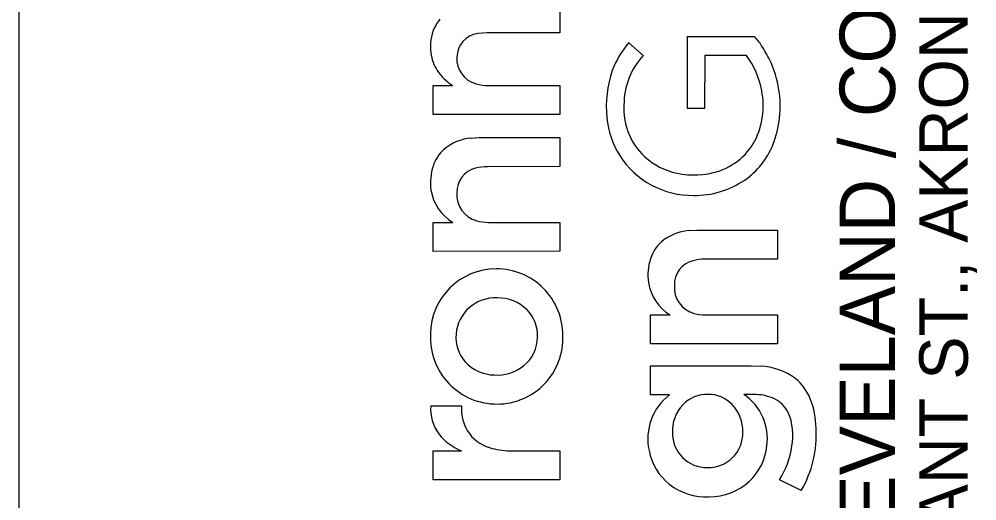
# Model space of a CAD drawing. Extents: x -0.4 to 34, y 0 to 22.
# Drawn here: x 32 to 32.984, y 3.094 to 3.59 of the extents above; entities that cross this region are included whole.
import ezdxf

# ---------------------------------------------------------------- set-up
doc = ezdxf.new("R2010")
doc.units = 0
doc.layers.add('SC_Scratch1', color=7, linetype='Continuous')
doc.layers.add('SH_Named_Boundary', color=7, linetype='Continuous')

msp = doc.modelspace()

# ---------------------------------------------------------------- linework, layer by layer
at = {"layer": 'SC_Scratch1'}
msp.add_line((32, 0.5), (32, 21.5), dxfattribs=at)
at = {"layer": 'SH_Named_Boundary'}
for p, q in [((32.55571, 3.60548), (32.55571, 3.57568)), ((32.4809, 3.57567), (32.47143, 3.57474)), ((32.55571, 3.57568), (32.4809, 3.57567)), ((32.62636, 3.56548), (32.64114, 3.55241)), ((32.6868, 3.57185), (32.75516, 3.57192)), ((32.6868, 3.49778), (32.6868, 3.57185)), ((32.70448, 3.55241), (32.70432, 3.49775)), ((32.74737, 3.55227), (32.70448, 3.55241)), ((32.42542, 3.49152), (32.42545, 3.52138)), ((32.42545, 3.52138), (32.44515, 3.52138)), ((32.48206, 3.52138), (32.55571, 3.52136)), ((32.55571, 3.52136), (32.55571, 3.49156)), ((32.70432, 3.49775), (32.6868, 3.49778)), ((32.75, 3.5), (32.75, 3.5)), ((32.55571, 3.49156), (32.42542, 3.49152)), ((32.46439, 3.46736), (32.47289, 3.46783)), ((32.47289, 3.46783), (32.55571, 3.46783)), ((32.55571, 3.46783), (32.55571, 3.43804)), ((32.55571, 3.43804), (32.4814, 3.43796)), ((32.42542, 3.38066), (32.44552, 3.38071)), ((32.42542, 3.35086), (32.42542, 3.38066)), ((32.48222, 3.38071), (32.55569, 3.38071)), ((32.55569, 3.38071), (32.55571, 3.35096)), ((32.68784, 3.3722), (32.69634, 3.37266)), ((32.69634, 3.37266), (32.77916, 3.37266)), ((32.77916, 3.37266), (32.77917, 3.34287)), ((32.55571, 3.35096), (32.42542, 3.35086)), ((32.77917, 3.34287), (32.70485, 3.3428)), ((32.64888, 3.2855), (32.66897, 3.28555)), ((32.64888, 3.25569), (32.64888, 3.2855)), ((32.70568, 3.28555), (32.77915, 3.28555)), ((32.77915, 3.28555), (32.77917, 3.25579)), ((32.77917, 3.25579), (32.64888, 3.25569)), ((32.6489, 3.20336), (32.64889, 3.23322)), ((32.64889, 3.23322), (32.75236, 3.23322)), ((32.75236, 3.23322), (32.76191, 3.23285)), ((32.66836, 3.20336), (32.6489, 3.20336)), ((32.75763, 3.20356), (32.74487, 3.20361)), ((32.42299, 3.19193), (32.45454, 3.19193)), ((32.42542, 3.14577), (32.45473, 3.14579)), ((32.42542, 3.11593), (32.42542, 3.14577)), ((32.50413, 3.14581), (32.55571, 3.14573)), ((32.55571, 3.14573), (32.55565, 3.11593)), ((32.55565, 3.11593), (32.42542, 3.11593)), ((32.8036, 3.10491), (32.7812, 3.11598))]:
    msp.add_line(p, q, dxfattribs=at)
for points in [[(32.48218, 3.60553), (32.55571, 3.60548), (32.55571, 3.57568), (32.4809, 3.57567), (32.47143, 3.57474)], [(32.62636, 3.56548), (32.64114, 3.55241)], [(32.74737, 3.55227), (32.70448, 3.55241), (32.70432, 3.49775), (32.6868, 3.49778), (32.6868, 3.57185), (32.75516, 3.57192)], [(32.42542, 3.49152), (32.42545, 3.52138), (32.44515, 3.52138)], [(32.48206, 3.52138), (32.55571, 3.52136), (32.55571, 3.49156), (32.42542, 3.49152)], [(32.46439, 3.46736), (32.47289, 3.46783), (32.55571, 3.46783), (32.55571, 3.43804), (32.4814, 3.43796)], [(32.42542, 3.35086), (32.42542, 3.38066), (32.44552, 3.38071)], [(32.48222, 3.38071), (32.55569, 3.38071), (32.55571, 3.35096), (32.42542, 3.35086)], [(32.68784, 3.3722), (32.69634, 3.37266), (32.77916, 3.37266), (32.77917, 3.34287), (32.70485, 3.3428)], [(32.64888, 3.25569), (32.64888, 3.2855), (32.66897, 3.28555)], [(32.70568, 3.28555), (32.77915, 3.28555), (32.77917, 3.25579), (32.64888, 3.25569)], [(32.66836, 3.20336), (32.6489, 3.20336), (32.64889, 3.23322), (32.75236, 3.23322), (32.76191, 3.23285)], [(32.75763, 3.20356), (32.74487, 3.20361)], [(32.42299, 3.19193), (32.45454, 3.19193)], [(32.50413, 3.14581), (32.55571, 3.14573), (32.55565, 3.11593), (32.42542, 3.11593)], [(32.42542, 3.11593), (32.42542, 3.14577), (32.45473, 3.14579)], [(32.8036, 3.10491), (32.7812, 3.11598)]]:
    msp.add_lwpolyline(points, dxfattribs=at)
for centre, radius, start, end in [((32.46194, 3.56452), 0.03875, 139.52447, 154.84698), ((32.46194, 3.56452), 0.03875, 139.52447, 154.84698), ((32.47144, 3.5612), 0.04877, 156.06382, 187.3493), ((32.47144, 3.5612), 0.04877, 156.06382, 187.3493), ((32.47421, 3.55056), 0.02434, 96.5532, 179.94902), ((32.47421, 3.55056), 0.02434, 96.5532, 179.94902), ((32.70163, 3.50187), 0.09855, 139.79476, 159.13696), ((32.70163, 3.50187), 0.09855, 139.79476, 159.13696), ((32.72498, 3.53937), 0.04438, 30.98913, 47.16099), ((32.72498, 3.53937), 0.04438, 30.98913, 47.16099), ((32.46461, 3.55974), 0.04181, 186.5579, 213.38846), ((32.46461, 3.55974), 0.04181, 186.5579, 213.38846), ((32.67091, 3.50018), 0.11106, 25.30315, 33.96179), ((32.67091, 3.50018), 0.11106, 25.30315, 33.96179), ((32.47608, 3.54863), 0.02628, 175.722, 255.78627), ((32.47608, 3.54863), 0.02628, 175.722, 255.78627), ((32.69899, 3.50079), 0.07753, 138.25804, 179.70064), ((32.69899, 3.50079), 0.07753, 138.25804, 179.70064), ((32.67889, 3.50099), 0.08556, 10.07509, 36.83189), ((32.67889, 3.50099), 0.08556, 10.07509, 36.83189), ((32.6704, 3.49987), 0.11166, 8.80339, 25.33484), ((32.6704, 3.49987), 0.11166, 8.80339, 25.33484), ((32.47886, 3.57078), 0.0598, 214.70433, 235.68724), ((32.47886, 3.57078), 0.0598, 214.70433, 235.68724), ((32.7187, 3.49968), 0.11536, 161.14379, 185.62812), ((32.7187, 3.49968), 0.11536, 161.14379, 185.62812), ((32.48195, 3.56518), 0.0438, 253.66719, 270.14979), ((32.48195, 3.56518), 0.0438, 253.66719, 270.14979), ((32.68425, 3.50057), 0.08036, 333.46689, 11.03668), ((32.68425, 3.50057), 0.08036, 333.46689, 11.03668), ((32.67564, 3.49977), 0.10649, 338.28866, 9.28548), ((32.67564, 3.49977), 0.10649, 338.28866, 9.28548), ((32.68811, 3.49732), 0.06676, 176.66577, 223.6912), ((32.68811, 3.49732), 0.06676, 176.66577, 223.6912), ((32.69336, 3.49699), 0.08987, 185.50773, 212.01294), ((32.69336, 3.49699), 0.08987, 185.50773, 212.01294), ((32.46871, 3.41767), 0.04988, 94.97056, 130.22484), ((32.46871, 3.41767), 0.04988, 94.97056, 130.22484), ((32.69868, 3.49547), 0.0652, 282.88151, 331.81475), ((32.69868, 3.49547), 0.0652, 282.88151, 331.81475), ((32.46348, 3.42602), 0.04016, 132.22383, 161.68229), ((32.46348, 3.42602), 0.04016, 132.22383, 161.68229), ((32.69835, 3.49168), 0.08241, 305.03061, 337.67573), ((32.69835, 3.49168), 0.08241, 305.03061, 337.67573), ((32.69211, 3.49748), 0.08908, 212.70222, 270.71399), ((32.69211, 3.49748), 0.08908, 212.70222, 270.71399), ((32.69045, 3.50011), 0.07039, 224.02147, 253.88), ((32.69045, 3.50011), 0.07039, 224.02147, 253.88), ((32.47872, 3.42158), 0.05602, 162.27398, 187.79173), ((32.47872, 3.42158), 0.05602, 162.27398, 187.79173), ((32.47482, 3.41206), 0.02498, 103.68683, 182.21395), ((32.47482, 3.41206), 0.02498, 103.68683, 182.21395), ((32.48108, 3.39196), 0.04601, 89.60515, 105.33026), ((32.48108, 3.39196), 0.04601, 89.60515, 105.33026), ((32.69318, 3.51254), 0.08309, 254.45353, 283.9512), ((32.69318, 3.51254), 0.08309, 254.45353, 283.9512), ((32.69429, 3.49979), 0.09138, 269.3273, 304.19632), ((32.69429, 3.49979), 0.09138, 269.3273, 304.19632), ((32.47027, 3.42141), 0.04763, 188.96462, 238.69865), ((32.47027, 3.42141), 0.04763, 188.96462, 238.69865), ((32.47735, 3.40897), 0.02757, 175.58441, 255.13816), ((32.47735, 3.40897), 0.02757, 175.58441, 255.13816), ((32.48183, 3.42286), 0.04215, 254.08913, 270.52838), ((32.48183, 3.42286), 0.04215, 254.08913, 270.52838), ((32.69216, 3.32251), 0.04988, 94.97056, 130.22484), ((32.69216, 3.32251), 0.04988, 94.97056, 130.22484), ((32.68694, 3.33085), 0.04016, 132.22383, 161.68229), ((32.68694, 3.33085), 0.04016, 132.22383, 161.68229), ((32.70217, 3.32642), 0.05602, 162.27398, 187.79173), ((32.70217, 3.32642), 0.05602, 162.27398, 187.79173), ((32.69828, 3.31689), 0.02498, 103.68683, 182.21395), ((32.69828, 3.31689), 0.02498, 103.68683, 182.21395), ((32.70453, 3.29679), 0.04601, 89.60515, 105.33026), ((32.70453, 3.29679), 0.04601, 89.60515, 105.33026), ((32.49014, 3.26543), 0.0674, 89.84756, 179.64047), ((32.49014, 3.26543), 0.0674, 89.84756, 179.64047), ((32.49057, 3.26474), 0.0681, 359.54009, 90.21138), ((32.49057, 3.26474), 0.0681, 359.54009, 90.21138), ((32.69372, 3.32624), 0.04763, 188.96462, 238.69865), ((32.69372, 3.32624), 0.04763, 188.96462, 238.69865), ((32.7008, 3.31381), 0.02757, 175.58441, 255.13816), ((32.7008, 3.31381), 0.02757, 175.58441, 255.13816), ((32.48923, 3.26263), 0.0404, 87.04809, 175.57259), ((32.48923, 3.26263), 0.0404, 87.04809, 175.57259), ((32.49204, 3.25999), 0.04299, 45.84264, 90.98008), ((32.49204, 3.25999), 0.04299, 45.84264, 90.98008), ((32.49458, 3.26421), 0.03821, 357.88569, 44.15902), ((32.49458, 3.26421), 0.03821, 357.88569, 44.15902), ((32.70529, 3.32769), 0.04215, 254.08913, 270.52838), ((32.70529, 3.32769), 0.04215, 254.08913, 270.52838), ((32.49083, 3.26209), 0.06819, 176.8344, 270.40384), ((32.49083, 3.26209), 0.06819, 176.8344, 270.40384), ((32.48729, 3.2625), 0.03848, 175.15378, 221.14706), ((32.48729, 3.2625), 0.03848, 175.15378, 221.14706), ((32.49123, 3.26139), 0.06749, 270.06243, 2.37759), ((32.49123, 3.26139), 0.06749, 270.06243, 2.37759), ((32.49446, 3.26318), 0.0383, 308.28936, 359.43468), ((32.49446, 3.26318), 0.0383, 308.28936, 359.43468), ((32.48919, 3.26607), 0.04228, 223.09994, 268.80895), ((32.48919, 3.26607), 0.04228, 223.09994, 268.80895), ((32.49096, 3.2679), 0.04418, 266.56515, 308.06078), ((32.49096, 3.2679), 0.04418, 266.56515, 308.06078), ((32.75907, 3.16789), 0.06503, 53.40344, 87.49062), ((32.75907, 3.16789), 0.06503, 53.40344, 87.49062), ((32.76517, 3.18039), 0.05141, 21.60748, 50.5577), ((32.76517, 3.18039), 0.05141, 21.60748, 50.5577), ((32.70292, 3.15813), 0.05692, 127.37482, 192.22468), ((32.70292, 3.15813), 0.05692, 127.37482, 192.22468), ((32.70693, 3.16927), 0.0346, 88.47302, 136.42562), ((32.70693, 3.16927), 0.0346, 88.47302, 136.42562), ((32.70814, 3.16963), 0.03424, 44.27195, 90.47623), ((32.70814, 3.16963), 0.03424, 44.27195, 90.47623), ((32.71421, 3.15829), 0.05472, 352.1125, 55.92295), ((32.71421, 3.15829), 0.05472, 352.1125, 55.92295), ((32.75666, 3.15725), 0.04633, 65.01687, 88.8011), ((32.75666, 3.15725), 0.04633, 65.01687, 88.8011), ((32.7626, 3.17155), 0.03085, 26.26808, 63.80301), ((32.7626, 3.17155), 0.03085, 26.26808, 63.80301), ((32.73069, 3.16714), 0.08835, 1.15143, 21.3627), ((32.73069, 3.16714), 0.08835, 1.15143, 21.3627), ((32.46616, 3.18882), 0.04329, 175.87313, 216.34747), ((32.46616, 3.18882), 0.04329, 175.87313, 216.34747), ((32.50087, 3.18948), 0.04639, 176.9688, 209.60636), ((32.50087, 3.18948), 0.04639, 176.9688, 209.60636), ((32.71141, 3.16602), 0.0401, 137.46739, 182.33237), ((32.71141, 3.16602), 0.0401, 137.46739, 182.33237), ((32.70368, 3.166), 0.03996, 358.57141, 43.53765), ((32.70368, 3.166), 0.03996, 358.57141, 43.53765), ((32.73565, 3.16154), 0.05953, 349.30734, 23.43071), ((32.73565, 3.16154), 0.05953, 349.30734, 23.43071), ((32.47466, 3.19716), 0.05511, 218.09809, 248.7907), ((32.47466, 3.19716), 0.05511, 218.09809, 248.7907), ((32.49514, 3.18814), 0.04079, 211.94466, 253.2028), ((32.49514, 3.18814), 0.04079, 211.94466, 253.2028), ((32.70645, 3.1637), 0.03511, 178.88208, 271.08374), ((32.70645, 3.1637), 0.03511, 178.88208, 271.08374), ((32.70818, 3.16404), 0.03546, 268.27882, 1.55016), ((32.70818, 3.16404), 0.03546, 268.27882, 1.55016), ((32.70538, 3.16244), 0.11383, 329.6388, 3.25998), ((32.70538, 3.16244), 0.11383, 329.6388, 3.25998), ((32.70988, 3.15708), 0.05887, 313.74196, 353.8554), ((32.70988, 3.15708), 0.05887, 313.74196, 353.8554), ((32.70738, 3.16334), 0.08771, 327.31495, 351.57478), ((32.70738, 3.16334), 0.08771, 327.31495, 351.57478), ((32.50465, 3.2165), 0.07069, 252.46555, 269.57296), ((32.50465, 3.2165), 0.07069, 252.46555, 269.57296), ((32.70463, 3.15696), 0.05837, 190.75182, 231.28919), ((32.70463, 3.15696), 0.05837, 190.75182, 231.28919), ((32.70632, 3.16112), 0.06269, 232.46061, 272.59022), ((32.70632, 3.16112), 0.06269, 232.46061, 272.59022), ((32.70954, 3.15901), 0.06051, 269.6361, 312.70877), ((32.70954, 3.15901), 0.06051, 269.6361, 312.70877)]:
    msp.add_arc(centre, radius, start, end, dxfattribs=at)

# ---------------------------------------------------------------- texts
for s, height, p in [('450 GRANT ST., AKRON, OH  44311', 0.0498462, (32.97489, 2.83738)), ('AKRON / CLEVELAND / COLUMBUS', 0.056969, (32.90012, 2.638))]:
    msp.add_text(s, height=height, rotation=90, dxfattribs=at).set_placement(p)

doc.saveas('drawing.dxf')
